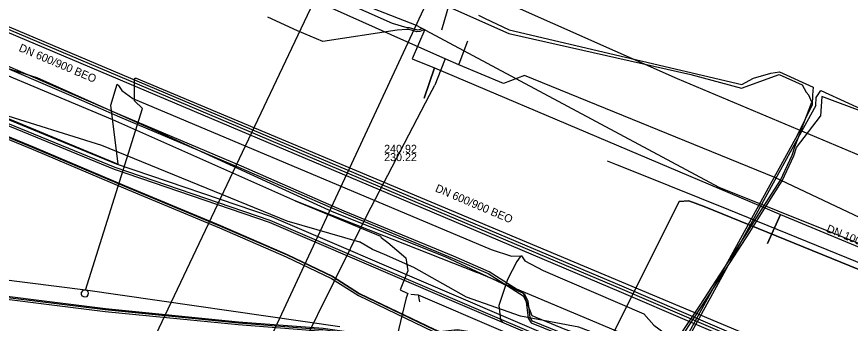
# Model space of a CAD drawing. Extents: x -596024 to -594475, y -1163820 to -1161957.
# Drawn here: x -594977.6 to -594894.3, y -1162135 to -1162104.3 of the extents above; entities that cross this region are included whole.
import ezdxf

# ---------------------------------------------------------------- set-up
doc = ezdxf.new("R2010")
doc.units = 0
for name, color, linetype in [('Vrstva 10', 7, 'Continuous'), ('Vrstva 12', 7, 'Continuous'), ('Vrstva 13', 7, 'Continuous'), ('Vrstva 15', 7, 'Continuous'), ('Vrstva 19', 7, 'Continuous'), ('Vrstva 42', 7, 'Continuous'), ('Vrstva 44', 7, 'Continuous'), ('Vrstva 53', 7, 'Continuous'), ('Vrstva 55', 7, 'Continuous'), ('Vrstva 58', 7, 'Continuous'), ('Vrstva 9', 7, 'Continuous')]:
    doc.layers.add(name, color=color, linetype=linetype)

msp = doc.modelspace()

# ---------------------------------------------------------------- linework, layer by layer
at = {"layer": 'Vrstva 10'}
for p, q in [((-594979.202, -1162104.986), (-594940.233, -1162121.484)), ((-594940.467, -1162122.036), (-594979.436, -1162105.539))]:
    msp.add_line(p, q, dxfattribs=at)
for points in [[(-594940.233, -1162121.484), (-594916.901, -1162131.369), (-594896.381, -1162140.194)], [(-594896.619, -1162140.746), (-594917.137, -1162131.921), (-594940.467, -1162122.036)]]:
    msp.add_lwpolyline(points, dxfattribs=at)
at = {"layer": 'Vrstva 12'}
for p, q in [((-594938.48, -1162132.02), (-594938.65, -1162132.45)), ((-594937.46, -1162132.16), (-594937.32, -1162132.85))]:
    msp.add_line(p, q, dxfattribs=at)
for points in [[(-594884.92, -1162121.76), (-594911.54, -1162110.55), (-594949.23, -1162093.8), (-595000, -1162072.9)], [(-595000, -1162102.21), (-594986.48, -1162106.88), (-594968, -1162114.63), (-594949.73, -1162122.77), (-594931.56, -1162129.92)], [(-594965.8, -1162112.75), (-594965.81, -1162110.59), (-594965.76, -1162110.5), (-594965.63, -1162110.49)], [(-594965.63, -1162110.49), (-594940.94, -1162120.86)], [(-594970.72, -1162131.69), (-594968.52, -1162124.7), (-594965.01, -1162113.53), (-594965.8, -1162112.75)], [(-594979.59, -1162113.93), (-594969.11, -1162117.2), (-594950.59, -1162124.75), (-594943.32, -1162126.88)], [(-594940.94, -1162120.86), (-594854.77, -1162157.03), (-594809.16, -1162176.45), (-594767.38, -1162194.31)], [(-594949.754, -1162122.759), (-594941.212, -1162126.301), (-594941.158, -1162126.434), (-594940.499, -1162126.937)], [(-594911.16, -1162139.42), (-594913.92, -1162138.24), (-594921.4, -1162135.39), (-594927.24, -1162134.29), (-594932.63, -1162132.4), (-594937.89, -1162129.44), (-594940.81, -1162128.13), (-594942.02, -1162127.63), (-594943.32, -1162126.88)], [(-594940.499, -1162126.937), (-594938.698, -1162128.48), (-594938.492, -1162129.768), (-594939.26, -1162131.65)], [(-594890.15, -1162147.05), (-594893.45, -1162145.88), (-594897.64, -1162144.17), (-594898.91, -1162143.62), (-594907.38, -1162140.1), (-594931.56, -1162129.92)], [(-594970.72, -1162131.69), (-594979.44, -1162130.61)], [(-594970.72, -1162131.69), (-594970.98, -1162131.74), (-594971.13, -1162131.93), (-594971.16, -1162132.1), (-594971.09, -1162132.28), (-594970.82, -1162132.38), (-594970.55, -1162132.33), (-594970.44, -1162132.17), (-594970.42, -1162132.01), (-594970.46, -1162131.86), (-594970.58, -1162131.73), (-594970.72, -1162131.69)], [(-594945.29, -1162135.36), (-594970.72, -1162131.69)], [(-594939.26, -1162131.65), (-594938.48, -1162132.02)], [(-594938.65, -1162132.45), (-594939.94, -1162137.9), (-594940.48, -1162142.29), (-594945.83, -1162158.49), (-594946.79, -1162162.06), (-594950.07, -1162173.52), (-594957.82, -1162196.23), (-594973.83, -1162243.01), (-594986.34, -1162280.9), (-594995.28, -1162307.97), (-595001.11, -1162334.64), (-595000.94, -1162335.11), (-594999.28, -1162352.34), (-594997.66, -1162363.83), (-594996.8, -1162372.69), (-594994.36, -1162396.57), (-594993.55, -1162422.69), (-594989.89, -1162471.94), (-594989.27, -1162484.26), (-594988.21, -1162493.1)], [(-594938.18, -1162132.1), (-594937.46, -1162132.16), (-594921, -1162139.23), (-594914.51, -1162140.99), (-594903.91, -1162145.02), (-594903.18, -1162145.52), (-594903.29, -1162147.39), (-594908.88, -1162159.69), (-594911.61, -1162165.81), (-594913.37, -1162170.27), (-594915.79, -1162175.82), (-594916.73, -1162178.42), (-594917.54, -1162180.59), (-594921.54, -1162194.47), (-594922.15, -1162196.85), (-594922.34, -1162197.5), (-594928.73, -1162215.2), (-594934.96, -1162232.34), (-594941.42, -1162249.91), (-594947.63, -1162267.23)]]:
    msp.add_lwpolyline(points, dxfattribs=at)
at = {"layer": 'Vrstva 13'}
for p, q in [((-594918.02, -1162119), (-594918.53, -1162118.79)), ((-594917.677, -1162119.138), (-594918.02, -1162119))]:
    msp.add_line(p, q, dxfattribs=at)
msp.add_lwpolyline([(-594835.54, -1162152.99), (-594840.08, -1162151.33), (-594856.62, -1162144.26), (-594867.65, -1162139.6), (-594884.22, -1162132.62), (-594889.78, -1162130.42), (-594906.41, -1162123.67), (-594915.274, -1162120.08), (-594917.677, -1162119.138)], dxfattribs=at)
at = {"layer": 'Vrstva 19'}
for points in [[(-594834.13, -1162150.42), (-594853.67, -1162141.96), (-594867.94, -1162135.71), (-594883.53, -1162129.07), (-594901.79, -1162120.42), (-594926.81, -1162110.23), (-594928.91, -1162111.02), (-594933.4, -1162109.17), (-594934.76, -1162108.55), (-594938.6, -1162106.86), (-594959.6, -1162097.43), (-594961.01, -1162092.97), (-594963.04, -1162092.01), (-594974.93, -1162087.13), (-594990.65, -1162080.96), (-595004.73, -1162074.95), (-595007.66, -1162073.38), (-595011.36, -1162071.28), (-595023.59, -1162063.83), (-595029.17, -1162061.22), (-595032.7, -1162061.12), (-595041.37, -1162057.15), (-595042.54, -1162053.99), (-595047.79, -1162051.63)], [(-594933.4, -1162109.17), (-594933.26, -1162108.78), (-594932.48, -1162106.77)], [(-594934.76, -1162108.55), (-594935.19, -1162109.66), (-594935.78, -1162111.19)], [(-594950.84, -1162140.46), (-594949.16, -1162137.51), (-594942.54, -1162124.16), (-594936.31, -1162112.2), (-594935.78, -1162111.19)]]:
    msp.add_lwpolyline(points, dxfattribs=at)
at = {"layer": 'Vrstva 42'}
for points in [[(-595076.85, -1162071.09), (-595070.609, -1162071.252), (-595067.572, -1162072.08), (-595066.504, -1162072.834), (-595064.969, -1162072.729), (-595057.526, -1162075.848), (-595046.042, -1162082.224), (-595037.826, -1162086.437), (-595033.97, -1162088.19), (-595033.845, -1162088.227), (-595023.376, -1162092.878), (-595010.628, -1162097.806), (-594996.365, -1162102.687), (-594987.338, -1162105.952), (-594979.828, -1162109.103), (-594975.585, -1162110.428), (-594962.839, -1162116.145), (-594952.248, -1162121.006), (-594946.053, -1162123.832), (-594934.8, -1162128.336), (-594926.951, -1162132.009), (-594926.08, -1162134.217), (-594922.779, -1162135.588), (-594916.95, -1162137.709)], [(-594917.505, -1162142.173), (-594917.883, -1162141.6), (-594917.261, -1162138.801), (-594917.912, -1162138.096), (-594926.022, -1162134.81), (-594926.254, -1162134.436), (-594926.473, -1162132.79), (-594926.803, -1162132.131), (-594930.363, -1162129.861), (-594933.931, -1162128.308), (-594944.851, -1162123.788), (-594946.4, -1162123.118), (-594955.1, -1162119.308), (-594967.241, -1162114.178), (-594972.11, -1162112.058), (-594980.58, -1162108.398)], [(-594980.66, -1162108.582), (-594972.19, -1162112.242), (-594967.319, -1162114.362), (-594955.18, -1162119.492), (-594946.48, -1162123.302), (-594944.929, -1162123.972), (-594934.009, -1162128.492), (-594930.457, -1162130.039), (-594926.957, -1162132.269), (-594926.667, -1162132.85), (-594926.446, -1162134.504), (-594926.158, -1162134.97), (-594918.028, -1162138.264), (-594917.479, -1162138.859), (-594918.097, -1162141.64), (-594917.597, -1162142.398)], [(-595050.25, -1162124.49), (-595039.596, -1162125.409), (-595026.932, -1162127.038), (-595017.39, -1162128.669), (-595009.367, -1162129.499), (-594997.514, -1162130.979), (-594984.744, -1162131.839), (-594968.747, -1162133.829), (-594955.433, -1162135.149), (-594946.986, -1162135.809), (-594942.51, -1162136.43), (-594937.641, -1162136.39), (-594933.514, -1162135.941), (-594928.427, -1162136.761), (-594924.123, -1162136.5), (-594919.817, -1162136.951), (-594917.127, -1162136.548), (-594914.857, -1162136.19), (-594913.634, -1162136.17)], [(-594841.6, -1162165.96), (-594861.847, -1162157.553), (-594879.336, -1162150.176), (-594896.797, -1162142.418), (-594908.73, -1162137.65), (-594910.38, -1162137.12), (-594913.61, -1162136.02), (-594914.87, -1162136.04), (-594917.15, -1162136.4), (-594919.82, -1162136.8), (-594924.12, -1162136.35), (-594928.42, -1162136.61), (-594933.51, -1162135.79), (-594937.65, -1162136.24), (-594942.5, -1162136.28), (-594946.97, -1162135.66), (-594955.42, -1162135), (-594968.73, -1162133.68), (-594984.73, -1162131.69)], [(-594984.716, -1162131.541), (-594968.713, -1162133.531), (-594955.407, -1162134.851), (-594946.954, -1162135.511), (-594942.49, -1162136.13), (-594937.659, -1162136.09), (-594933.506, -1162135.639), (-594928.413, -1162136.459), (-594924.117, -1162136.2), (-594919.823, -1162136.649), (-594917.173, -1162136.252), (-594914.883, -1162135.89), (-594913.586, -1162135.87), (-594910.333, -1162136.978), (-594908.679, -1162137.509), (-594896.739, -1162142.28), (-594879.276, -1162150.038), (-594861.789, -1162157.415), (-594841.589, -1162165.801)]]:
    msp.add_lwpolyline(points, dxfattribs=at)
at = {"layer": 'Vrstva 44'}
for points in [[(-595066.105, -1162080.68), (-595062.648, -1162081.161), (-595060.545, -1162081.694), (-595054.166, -1162084.398), (-595048.287, -1162087.117), (-595041.419, -1162089.957), (-595034.638, -1162092.727), (-595027.287, -1162095.887), (-595020.408, -1162098.857), (-595012.508, -1162102.227), (-595006.858, -1162104.577), (-595000.518, -1162107.237), (-594990.789, -1162111.317), (-594975.868, -1162117.447), (-594966.828, -1162121.287), (-594957.228, -1162125.287), (-594950.556, -1162128.178), (-594946.028, -1162130.341), (-594943.328, -1162132.061), (-594935.876, -1162135.638), (-594926.073, -1162139.775), (-594923.737, -1162140.504), (-594923.306, -1162140.637), (-594922.193, -1162141.292)], [(-595048.367, -1162087.301), (-595041.495, -1162090.141), (-595034.716, -1162092.911), (-595027.367, -1162096.071), (-595020.486, -1162099.041), (-595012.586, -1162102.411), (-595006.936, -1162104.761), (-595000.596, -1162107.421), (-594990.865, -1162111.501), (-594975.946, -1162117.631), (-594966.906, -1162121.471), (-594957.306, -1162125.471), (-594950.638, -1162128.36), (-594946.126, -1162130.517), (-594943.426, -1162132.237), (-594935.958, -1162135.82), (-594926.141, -1162139.963), (-594923.797, -1162140.694)], [(-594931.419, -1162104.207), (-594930.811, -1162104.489), (-594928.341, -1162105.66)], [(-594928.341, -1162105.66), (-594905.09, -1162111.12), (-594903.93, -1162110.51), (-594902.21, -1162109.98), (-594901.34, -1162109.87), (-594897.964, -1162111.402), (-594898.032, -1162112.204), (-594898.072, -1162113.187)], [(-594897.711, -1162113.224), (-594897.659, -1162112.443), (-594897.203, -1162111.73), (-594891.67, -1162114.27), (-594878.67, -1162119), (-594873.42, -1162120.84), (-594854.55, -1162127.94), (-594839.87, -1162134.11), (-594825.09, -1162140.78), (-594817.14, -1162144.35), (-594807.51, -1162148.58), (-594782.23, -1162159.7), (-594776.89, -1162161.97), (-594769.64, -1162165.13), (-594762.3, -1162168.5), (-594754.5, -1162172.04), (-594749.77, -1162173.9), (-594746.29, -1162175.24), (-594745.226, -1162175.919)], [(-594897.711, -1162113.224), (-594899.327, -1162116.203), (-594914.275, -1162143.43), (-594914.877, -1162143.814), (-594915.93, -1162143.835), (-594918.319, -1162143.304), (-594919.57, -1162144.214), (-594928.47, -1162171.229), (-594938.587, -1162197.497), (-594939.94, -1162199.983), (-594948.355, -1162223.097), (-594959.108, -1162256.412), (-594959.244, -1162256.859), (-594960.697, -1162257.338), (-594962.509, -1162256.765), (-594967.966, -1162254.906), (-594973.009, -1162253.137), (-594974.955, -1162249.758), (-594981.381, -1162245.435), (-594988.082, -1162242.336), (-594992.7, -1162240.377), (-594999.092, -1162238.351), (-595000.799, -1162237.338), (-595000.448, -1162236.382)], [(-594988.666, -1162240.447), (-594988.908, -1162241.782), (-594987.998, -1162242.153), (-594981.353, -1162245.28), (-594974.83, -1162249.699), (-594972.891, -1162253.002), (-594967.908, -1162254.744), (-594962.542, -1162256.591), (-594960.679, -1162257.077), (-594959.389, -1162256.632), (-594959.298, -1162256.35), (-594948.545, -1162223.033), (-594940.126, -1162199.911), (-594938.856, -1162197.362), (-594928.658, -1162171.161), (-594919.74, -1162144.09), (-594918.363, -1162143.09), (-594915.91, -1162143.635), (-594914.937, -1162143.616), (-594914.425, -1162143.288), (-594899.507, -1162116.113), (-594898.072, -1162113.187)]]:
    msp.add_lwpolyline(points, dxfattribs=at)
at = {"layer": 'Vrstva 53'}
for points in [[(-594878.712, -1161956.88), (-594977.6, -1162165.5), (-594985.247, -1162190.772)], [(-594868.666, -1161956.88), (-594968, -1162170.4), (-594974.533, -1162195.382)]]:
    msp.add_lwpolyline(points, dxfattribs=at)
at = {"layer": 'Vrstva 55'}
for points in [[(-594935.082, -1162105.667), (-594930.52, -1162089.92), (-594923.608, -1162073.889)], [(-595058.73, -1162080.33), (-595036.98, -1162089.76), (-595035.15, -1162086.29), (-595034.75, -1162086.58), (-595036.55, -1162089.98), (-595013.23, -1162099.96), (-595011.37, -1162096.14), (-595010.86, -1162096.32), (-595012.76, -1162100.14), (-594998.4, -1162106.21), (-594982.82, -1162112.73), (-594967.44, -1162119.08), (-594968.17, -1162113.18), (-594967.54, -1162111.09)], [(-594977.82, -1162089.64), (-594977.55, -1162089.48), (-594977.09, -1162089.76), (-594973.44, -1162091.455), (-594970.02, -1162092.96), (-594963.54, -1162096.55), (-594962.02, -1162097.76), (-594961.22, -1162098.05), (-594958.93, -1162097.72), (-594958.44, -1162097.55), (-594956.98, -1162097.68), (-594956.44, -1162097.68), (-594940.04, -1162105), (-594938.58, -1162105.42), (-594938.34, -1162105.42), (-594937.57, -1162105.65), (-594937.33, -1162105.61), (-594937.04, -1162105.51)], [(-594936.79, -1162105.62), (-594937.28, -1162105.81), (-594937.59, -1162105.85), (-594938.37, -1162105.62), (-594938.58, -1162105.62), (-594939.56, -1162105.68), (-594947, -1162106.82), (-594949.53, -1162105.76), (-594952.47, -1162104.39)], [(-594936.79, -1162105.62), (-594938.06, -1162108.554), (-594935.82, -1162109.46), (-594936.87, -1162112.5), (-594935.82, -1162109.46), (-594901.22, -1162124.12), (-594902.54, -1162127.03), (-594901.22, -1162124.12), (-594875.47, -1162134.82), (-594871.07, -1162137.32), (-594872.17, -1162139.55)], [(-594967.54, -1162111.09), (-594967.419, -1162111.217), (-594967.07, -1162111.74), (-594965.97, -1162112.52), (-594930.14, -1162127.63), (-594928.12, -1162128.31), (-594927.13, -1162128.26), (-594926.8, -1162128.76), (-594924.95, -1162129.72), (-594914.91, -1162134.08), (-594913.88, -1162135.21), (-594912.76, -1162136.04), (-594899.72, -1162141.53), (-594897.75, -1162142.26), (-594895.75, -1162142.38), (-594895.26, -1162142.67), (-594894.98, -1162142.02), (-594894.83, -1162141.93), (-594894.811, -1162142.104), (-594895.1, -1162142.8), (-594894.85, -1162143.2), (-594894.85, -1162143.56)], [(-594927.13, -1162128.26), (-594927.25, -1162128.35), (-594927.6, -1162128.82), (-594928.54, -1162130.62), (-594929.4, -1162133.23), (-594929.21, -1162134.65), (-594928.99, -1162134.91)]]:
    msp.add_lwpolyline(points, dxfattribs=at)
at = {"layer": 'Vrstva 58'}
for points in [[(-595070.082, -1162044.552), (-595044.512, -1162055.396), (-595024.001, -1162066.113), (-595000.874, -1162079.189), (-594977.696, -1162089.547), (-594937.648, -1162105.187), (-594907.394, -1162121.391), (-594889.549, -1162128.57), (-594872.678, -1162139.852), (-594855.521, -1162146.975), (-594837.445, -1162154.525)], [(-595048.408, -1162050.859), (-595043.488, -1162052.629), (-595035.238, -1162056.379), (-595030.598, -1162058.589), (-595026.268, -1162061.279), (-595021.108, -1162063.639), (-595013.438, -1162068.399), (-595003.938, -1162073.489), (-595000.568, -1162075.459), (-594991.078, -1162079.249), (-594983.368, -1162082.249), (-594975.438, -1162086.149), (-594962.088, -1162091.289), (-594954.498, -1162094.479), (-594940.448, -1162100.609), (-594931.311, -1162104.727), (-594928.375, -1162106.017), (-594910.192, -1162110.138), (-594905.126, -1162111.489), (-594901.365, -1162110.121), (-594899.057, -1162111.147), (-594898.67, -1162111.91)], [(-594941.094, -1162198.987), (-594920.43, -1162143.658), (-594919.617, -1162140.938), (-594919.37, -1162139.932), (-594919.014, -1162139.223), (-594918.681, -1162138.689), (-594919.617, -1162138.478), (-594921.764, -1162138.03), (-594934.783, -1162132.453), (-594952.315, -1162124.916), (-594967.814, -1162119.636), (-595002.082, -1162105.573), (-595032.074, -1162092.561), (-595055.072, -1162082.532)], [(-594917.46, -1162138.59), (-594918.145, -1162138.56), (-594921.7, -1162137.83), (-594934.7, -1162132.26), (-594952.24, -1162124.72), (-594967.74, -1162119.44), (-595002, -1162105.38), (-595031.99, -1162092.37), (-595054.99, -1162082.34)], [(-594917.46, -1162138.59), (-594918.145, -1162138.56), (-594921.7, -1162137.83), (-594934.7, -1162132.26), (-594952.24, -1162124.72), (-594967.74, -1162119.44), (-595002, -1162105.38), (-595031.99, -1162092.37), (-595054.99, -1162082.34)], [(-594919.368, -1162137.929), (-594921.585, -1162137.464), (-594934.55, -1162131.91), (-594952.103, -1162124.364), (-594967.606, -1162119.083), (-595001.852, -1162105.029), (-595031.838, -1162092.02), (-595054.841, -1162081.989)], [(-595041.397, -1162089.909), (-595034.617, -1162092.679), (-595027.267, -1162095.839), (-595020.387, -1162098.809), (-595012.487, -1162102.179), (-595006.837, -1162104.529), (-595000.497, -1162107.189), (-594990.767, -1162111.269), (-594975.847, -1162117.399), (-594966.807, -1162121.239), (-594957.207, -1162125.239), (-594950.537, -1162128.129), (-594946.007, -1162130.299), (-594943.307, -1162132.019), (-594935.857, -1162135.589), (-594926.057, -1162139.729), (-594922.857, -1162140.779), (-594922.177, -1162141.239), (-594919.817, -1162141.829), (-594919.607, -1162143.459), (-594919.657, -1162143.929), (-594926.607, -1162162.569), (-594933.427, -1162180.919), (-594940.387, -1162199.549)], [(-594939.981, -1162199.469), (-594919.291, -1162144.075), (-594918.955, -1162143.309), (-594918.4, -1162143.331), (-594915.977, -1162144.258), (-594915.412, -1162144.194), (-594915.048, -1162143.885), (-594913.459, -1162141.144), (-594911.218, -1162136.132), (-594909.264, -1162133.195), (-594904.464, -1162125.806), (-594902.965, -1162123.407), (-594901.238, -1162120.682), (-594900.073, -1162118.203), (-594899.805, -1162117.369), (-594898.1, -1162112.89), (-594898.39, -1162112.21), (-594898.67, -1162111.91)], [(-594840.047, -1162134.517), (-594854.714, -1162128.353), (-594858.2, -1162127.025), (-594871.45, -1162121.921), (-594897.092, -1162112.344), (-594897.23, -1162114.29)], [(-594939.797, -1162199.549), (-594919.104, -1162144.145), (-594918.846, -1162143.509), (-594918.44, -1162143.529), (-594916.003, -1162144.462), (-594915.328, -1162144.386), (-594914.892, -1162144.015), (-594913.281, -1162141.236), (-594911.042, -1162136.228), (-594909.096, -1162133.305), (-594904.296, -1162125.914), (-594902.795, -1162123.513), (-594901.062, -1162120.778), (-594899.887, -1162118.277), (-594899.615, -1162117.431), (-594897.23, -1162114.29)], [(-594881.54, -1162134.66), (-594886.2, -1162132.57), (-594908.87, -1162123.34), (-594910.38, -1162122.75), (-594911.37, -1162122.84), (-594919.74, -1162139.57), (-594920.46, -1162141.06), (-594927.96, -1162161.23), (-594929.06, -1162164.03), (-594931.14, -1162169.7), (-594932.08, -1162172.59), (-594942.61, -1162200.07)], [(-594942.61, -1162200.07), (-594932.08, -1162172.59), (-594931.14, -1162169.7), (-594929.06, -1162164.03), (-594927.96, -1162161.23), (-594920.46, -1162141.06), (-594919.74, -1162139.57), (-594911.37, -1162122.84), (-594910.38, -1162122.75), (-594908.87, -1162123.34), (-594886.2, -1162132.57), (-594881.54, -1162134.66), (-594872.81, -1162138.34), (-594871.48, -1162138.9), (-594855.8, -1162145.62), (-594837.62, -1162153.37)]]:
    msp.add_lwpolyline(points, dxfattribs=at)
at = {"layer": 'Vrstva 9'}
msp.add_line((-594940.35, -1162121.76), (-594979.319, -1162105.262), dxfattribs=at)
msp.add_lwpolyline([(-594896.5, -1162140.47), (-594917.019, -1162131.645), (-594940.35, -1162121.76)], dxfattribs=at)

# ---------------------------------------------------------------- texts
at = {"layer": 'Vrstva 12'}
for rotation, p in [(337.05478, (-594977.445, -1162107.755)), (336.99344, (-594935.816, -1162121.801))]:
    msp.add_text('DN 600/900 BEO', height=0.8, rotation=rotation, dxfattribs=at).set_placement(p)
for s, p in [('240.92', (-594940.854, -1162117.959)), ('230.22', (-594940.854, -1162118.791))]:
    msp.add_text(s, height=0.8, dxfattribs=at).set_placement(p)
at = {"layer": 'Vrstva 15'}
msp.add_text('DN 100 LT', height=0.8, rotation=337.93051, dxfattribs=at).set_placement((-594896.705, -1162125.844))

doc.saveas('drawing.dxf')
